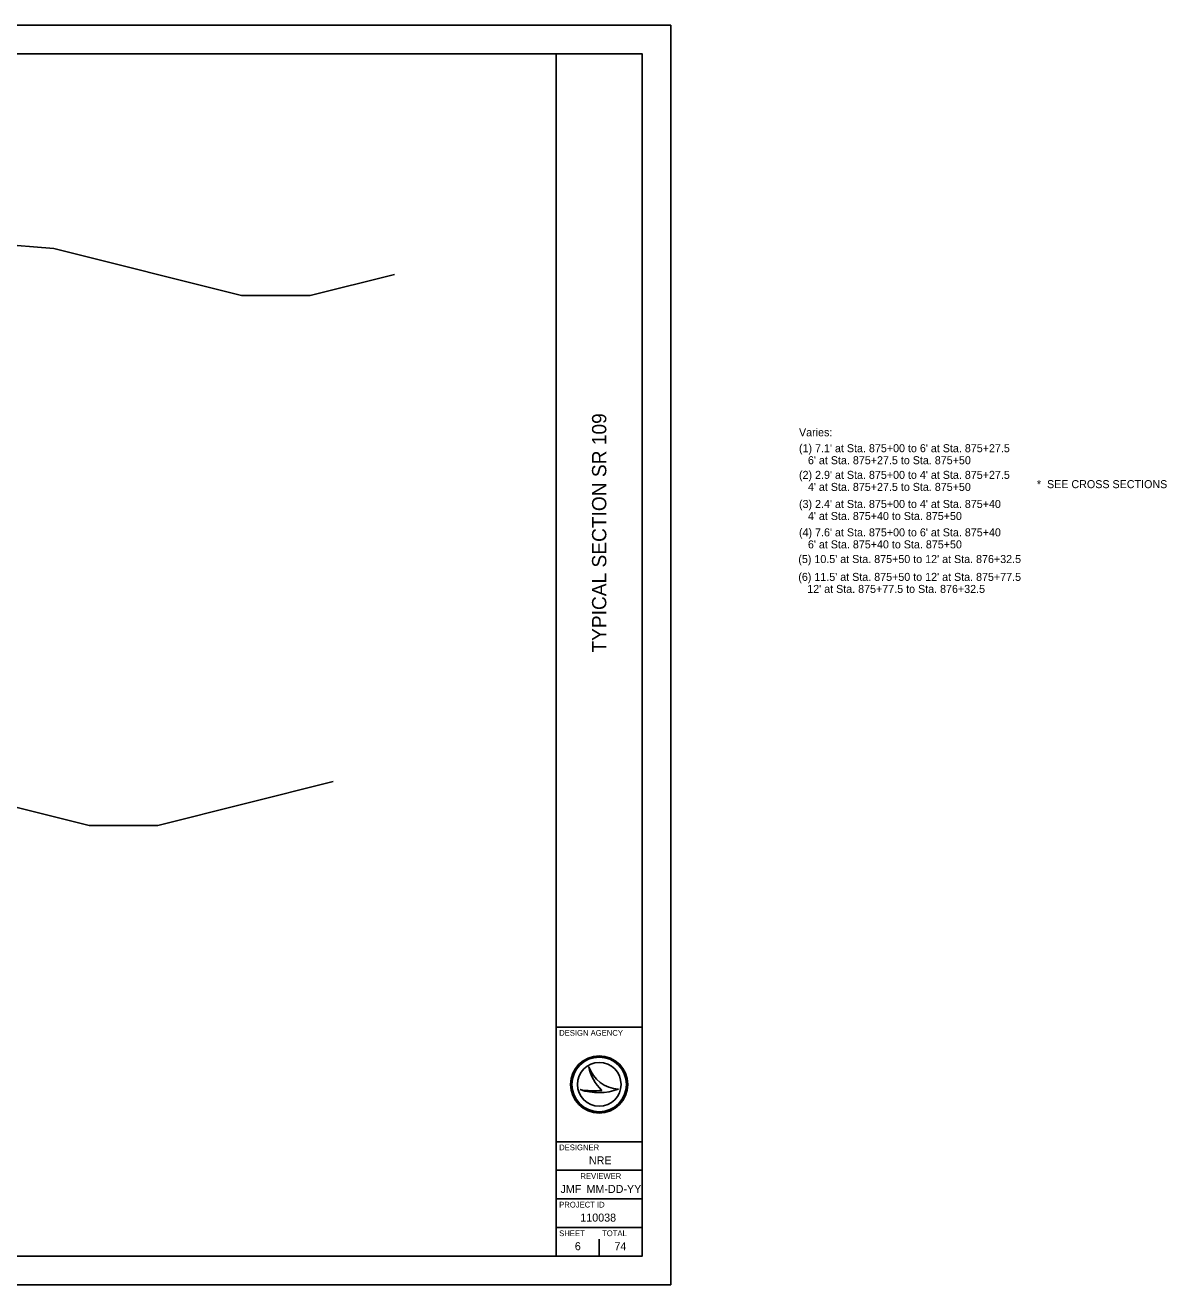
# Model space of a CAD drawing. Extents: x -31 to 213, y -26 to 110.
# Drawn here: x 113.6 to 213.3, y 0 to 110 of the extents above; entities that cross this region are included whole.
import ezdxf

# ---------------------------------------------------------------- set-up
doc = ezdxf.new("R2010")
doc.units = 0
for name, color, linetype in [('SH_Border', 7, 'Continuous'), ('SH_Cut_Line', 7, 'Continuous'), ('SH_Data', 7, 'Continuous'), ('SH_Text', 7, 'Continuous'), ('XS_X_Ground_Line', 7, 'Continuous')]:
    doc.layers.add(name, color=color, linetype=linetype)

msp = doc.modelspace()

# ---------------------------------------------------------------- linework, layer by layer
at = {"layer": 'SH_Border'}
for p, q in [((160, 2.5), (160, 107.5)), ((160, 22.5), (167.5, 22.5)), ((160, 12.5), (167.5, 12.5)), ((160, 10), (167.5, 10)), ((160, 7.5), (167.5, 7.5)), ((160, 5), (167.5, 5))]:
    msp.add_line(p, q, dxfattribs=at)
msp.add_lwpolyline([(7.5, 107.5), (167.5, 107.5), (167.5, 2.5), (7.5, 2.5)], close=True, dxfattribs=at)
at = {"layer": 'SH_Cut_Line'}
msp.add_lwpolyline([(0, 0), (170, 0), (170, 110), (0, 110)], close=True, dxfattribs=at)
at = {"layer": 'SH_Data'}
for p, q in [((162.84, 19.05), (162.84, 19.05)), ((162.09, 17.05), (162.09, 17.05)), ((163.75, 17.5), (163.75, 17.5)), ((165.44, 17.09), (165.44, 17.09)), ((161.87, 3.38), (161.87, 3.38)), ((163.75, 2.5), (163.75, 4))]:
    msp.add_line(p, q, dxfattribs=at)
for radius in [2.5, 2.38, 2.38, 1.91]:
    msp.add_circle((163.75, 17.5), radius, dxfattribs=at)
for centre, radius, start, end in [((165.58, 19.99), 2.9, 198.9257, 198.9319), ((166.73, 19.85), 3.98, 191.6379, 191.6421), ((165.58, 19.99), 2.9, 198.9319, 267.1657), ((166.73, 19.85), 3.98, 191.6421, 226.0947), ((163.7, 21.85), 5.07, 251.4576, 290.0832), ((163.24, 23.27), 6.33, 259.4964, 259.4995), ((163.7, 21.85), 5.07, 251.4527, 251.4576), ((163.24, 23.27), 6.33, 259.4995, 276.6672)]:
    msp.add_arc(centre, radius, start, end, dxfattribs=at)
at = {"layer": 'XS_X_Ground_Line'}
for p, q in [((107.12, 91.24), (116.12, 90.49)), ((116.12, 90.49), (132.51, 86.39)), ((138.51, 86.39), (145.86, 88.23)), ((138.51, 86.39), (132.51, 86.39)), ((102.8, 44.21), (119.19, 40.11)), ((125.19, 40.11), (140.51, 43.94)), ((125.19, 40.11), (119.19, 40.11))]:
    msp.add_line(p, q, dxfattribs=at)

# ---------------------------------------------------------------- texts
at = {"layer": 'SH_Data'}
msp.add_text('TYPICAL SECTION SR 109', height=1.25, rotation=90, dxfattribs=at).set_placement((164.37, 55.21))
for s, height, p in [('DESIGN AGENCY', 0.5, (160.25, 21.75)), ('DESIGNER', 0.5, (160.25, 11.75)), ('NRE', 0.7, (162.85, 10.52)), ('REVIEWER', 0.5, (162.11, 9.25)), ('JMF', 0.7, (160.37, 8.02)), ('MM-DD-YY', 0.7, (162.64, 8.02)), ('PROJECT ID', 0.5, (160.25, 6.75)), ('110038', 0.7, (162.1, 5.52)), ('SHEET', 0.5, (160.25, 4.25)), ('TOTAL', 0.5, (164, 4.25)), ('6', 0.7, (161.62, 3.02)), ('74', 0.7, (165.08, 3.02))]:
    msp.add_text(s, height=height, dxfattribs=at).set_placement(p)
at = {"layer": 'SH_Text'}
for s, p in [('Varies:       ', (181.2, 74.1)), ("(1) 7.1' at Sta. 875+00 to 6' at Sta. 875+27.5", (181.2, 72.71)), ("   6' at Sta. 875+27.5 to Sta. 875+50", (181.2, 71.66)), ("(2) 2.9' at Sta. 875+00 to 4' at Sta. 875+27.5", (181.2, 70.38)), ("   4' at Sta. 875+27.5 to Sta. 875+50", (181.2, 69.33)), ('*  SEE CROSS SECTIONS', (201.98, 69.57)), ("(3) 2.4' at Sta. 875+00 to 4' at Sta. 875+40", (181.2, 67.84)), ("   4' at Sta. 875+40 to Sta. 875+50", (181.2, 66.79)), ("(4) 7.6' at Sta. 875+00 to 6' at Sta. 875+40", (181.2, 65.36)), ("   6' at Sta. 875+40 to Sta. 875+50", (181.2, 64.31)), ("(5) 10.5' at Sta. 875+50 to 12' at Sta. 876+32.5   ", (181.14, 63.03)), ("(6) 11.5' at Sta. 875+50 to 12' at Sta. 875+77.5", (181.14, 61.47)), ("   12' at Sta. 875+77.5 to Sta. 876+32.5", (181.14, 60.42))]:
    msp.add_text(s, height=0.7, dxfattribs=at).set_placement(p)

doc.saveas('drawing.dxf')
